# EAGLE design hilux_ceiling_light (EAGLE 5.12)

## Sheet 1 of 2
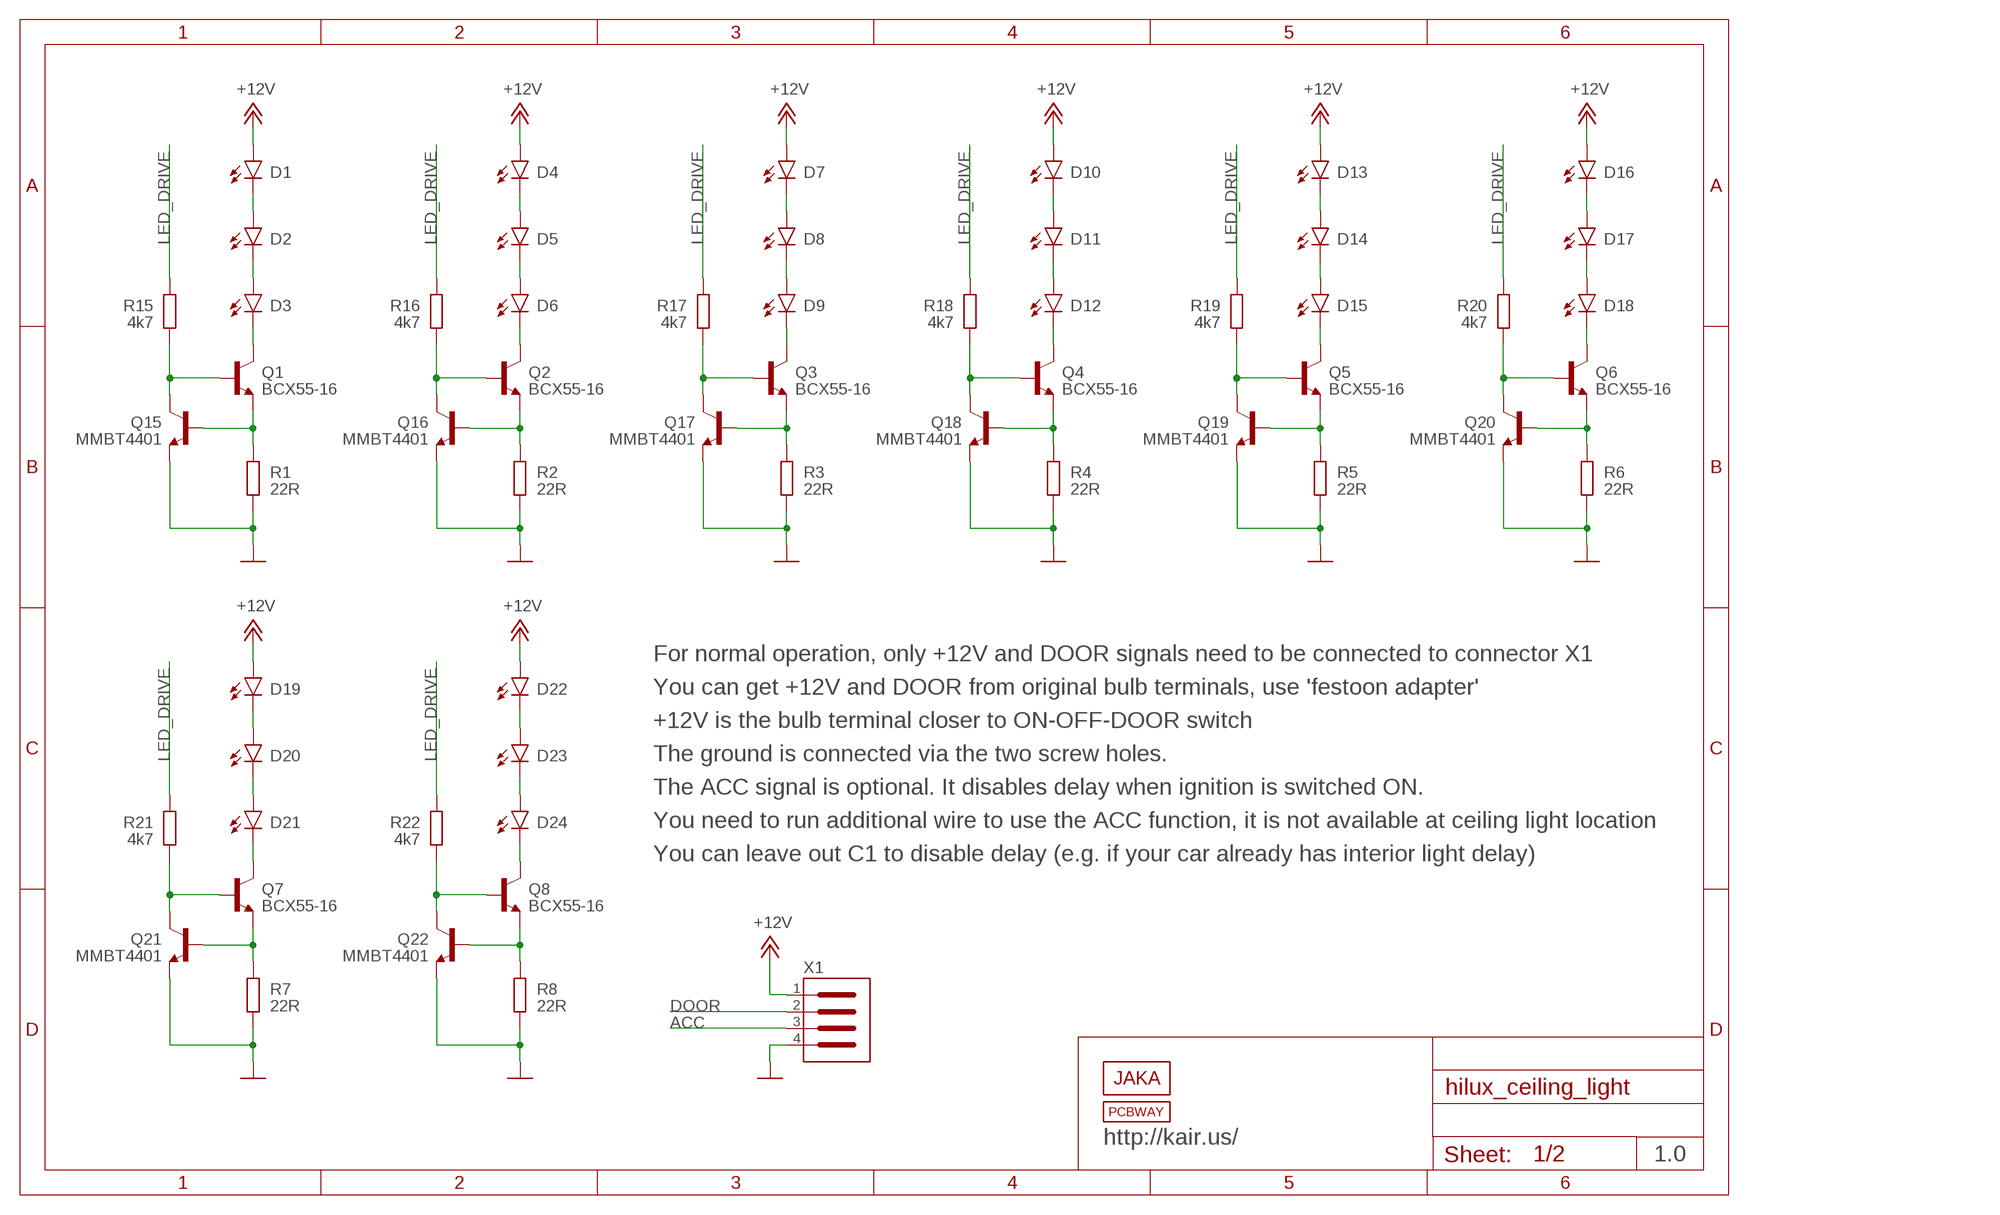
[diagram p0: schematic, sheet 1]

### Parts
D1  CREE_JE2835  [CREE_J2835]
D2  CREE_JE2835  [CREE_J2835]
D3  CREE_JE2835  [CREE_J2835]
D4  CREE_JE2835  [CREE_J2835]
D5  CREE_JE2835  [CREE_J2835]
D6  CREE_JE2835  [CREE_J2835]
D7  CREE_JE2835  [CREE_J2835]
D8  CREE_JE2835  [CREE_J2835]
D9  CREE_JE2835  [CREE_J2835]
D10  CREE_JE2835  [CREE_J2835]
D11  CREE_JE2835  [CREE_J2835]
D12  CREE_JE2835  [CREE_J2835]
D13  CREE_JE2835  [CREE_J2835]
D14  CREE_JE2835  [CREE_J2835]
D15  CREE_JE2835  [CREE_J2835]
D16  CREE_JE2835  [CREE_J2835]
D17  CREE_JE2835  [CREE_J2835]
D18  CREE_JE2835  [CREE_J2835]
D19  CREE_JE2835  [CREE_J2835]
D20  CREE_JE2835  [CREE_J2835]
D21  CREE_JE2835  [CREE_J2835]
D22  CREE_JE2835  [CREE_J2835]
D23  CREE_JE2835  [CREE_J2835]
D24  CREE_JE2835  [CREE_J2835]
LOGO1  PCBWAY_LOGO_SILK_TINY  [PCBWAY_LOGO_SILK_TINY]
Q1  BCX55-16  -NPN-SOT89-BCE  [SOT89-BCE]
Q2  BCX55-16  -NPN-SOT89-BCE  [SOT89-BCE]
Q3  BCX55-16  -NPN-SOT89-BCE  [SOT89-BCE]
Q4  BCX55-16  -NPN-SOT89-BCE  [SOT89-BCE]
Q5  BCX55-16  -NPN-SOT89-BCE  [SOT89-BCE]
Q6  BCX55-16  -NPN-SOT89-BCE  [SOT89-BCE]
Q7  BCX55-16  -NPN-SOT89-BCE  [SOT89-BCE]
Q8  BCX55-16  -NPN-SOT89-BCE  [SOT89-BCE]
Q15  MMBT4401  MMBT4401LT1-NPN-SOT-23-BEC  [SOT-23]
Q16  MMBT4401  MMBT4401LT1-NPN-SOT-23-BEC  [SOT-23]
Q17  MMBT4401  MMBT4401LT1-NPN-SOT-23-BEC  [SOT-23]
Q18  MMBT4401  MMBT4401LT1-NPN-SOT-23-BEC  [SOT-23]
Q19  MMBT4401  MMBT4401LT1-NPN-SOT-23-BEC  [SOT-23]
Q20  MMBT4401  MMBT4401LT1-NPN-SOT-23-BEC  [SOT-23]
Q21  MMBT4401  MMBT4401LT1-NPN-SOT-23-BEC  [SOT-23]
Q22  MMBT4401  MMBT4401LT1-NPN-SOT-23-BEC  [SOT-23]
R1  22R  R-EU_R0805  [R0805]
R2  22R  R-EU_R0805  [R0805]
R3  22R  R-EU_R0805  [R0805]
R4  22R  R-EU_R0805  [R0805]
R5  22R  R-EU_R0805  [R0805]
R6  22R  R-EU_R0805  [R0805]
R7  22R  R-EU_R0805  [R0805]
R8  22R  R-EU_R0805  [R0805]
R15  4k7  R-EU_R0805  [R0805]
R16  4k7  R-EU_R0805  [R0805]
R17  4k7  R-EU_R0805  [R0805]
R18  4k7  R-EU_R0805  [R0805]
R19  4k7  R-EU_R0805  [R0805]
R20  4k7  R-EU_R0805  [R0805]
R21  4k7  R-EU_R0805  [R0805]
R22  4k7  R-EU_R0805  [R0805]
U$1  JAKA_LOGO_MASK_TINY  [JAKA_MASK_TINY]
X1  CON_HEADER_4P  [HEADER_1X04_STAGGERED]

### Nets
+12V: D1.A D4.A D7.A D10.A D13.A D16.A D19.A D22.A X1.1 ; also sheet 2
ACC: X1.3 ; also sheet 2
DOOR: X1.2 ; also sheet 2
GND: Q15.2(E) Q16.2(E) Q17.2(E) Q18.2(E) Q19.2(E) Q20.2(E) Q21.2(E) Q22.2(E) R1.2 R2.2 R3.2 R4.2 R5.2 R6.2 R7.2 R8.2 X1.4 ; also sheet 2
LED_DRIVE: R15.1 R16.1 R17.1 R18.1 R19.1 R20.1 R21.1 R22.1 ; also sheet 2
N$1: Q1.E Q15.1(B) R1.1
N$2: Q1.B Q15.3(C) R15.2
N$4: D2.K D3.A
N$5: D1.K D2.A
N$7: Q2.E Q16.1(B) R2.1
N$8: Q2.B Q16.3(C) R16.2
N$10: D5.K D6.A
N$11: D4.K D5.A
N$13: Q3.E Q17.1(B) R3.1
N$14: Q3.B Q17.3(C) R17.2
N$17: D8.K D9.A
N$18: D7.K D8.A
N$19: Q4.E Q18.1(B) R4.1
N$20: Q4.B Q18.3(C) R18.2
N$22: D11.K D12.A
N$23: D10.K D11.A
N$25: Q5.E Q19.1(B) R5.1
N$26: Q5.B Q19.3(C) R19.2
N$28: D14.K D15.A
N$29: D13.K D14.A
N$31: Q6.E Q20.1(B) R6.1
N$32: Q6.B Q20.3(C) R20.2
N$34: D17.K D18.A
N$35: D16.K D17.A
N$43: Q7.E Q21.1(B) R7.1
N$44: Q7.B Q21.3(C) R21.2
N$46: D20.K D21.A
N$47: D19.K D20.A
N$48: Q8.E Q22.1(B) R8.1
N$49: Q8.B Q22.3(C) R22.2
N$51: D23.K D24.A
N$52: D22.K D23.A
Q1_HEAT: D3.K Q1.C@1(C)
Q2_HEAT: D6.K Q2.C@1(C)
Q3_HEAT: D9.K Q3.C@1(C)
Q4_HEAT: D12.K Q4.C@1(C)
Q5_HEAT: D15.K Q5.C@1(C)
Q6_HEAT: D18.K Q6.C@1(C)
Q7_HEAT: D21.K Q7.C@1(C)
Q8_HEAT: D24.K Q8.C@1(C)

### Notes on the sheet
- For normal operation, only +12V and DOOR signals need to be connected to connector X1
- You can get +12V and DOOR from original bulb terminals, use 'festoon adapter'
- +12V is the bulb terminal closer to ON-OFF-DOOR switch
- The ground is connected via the two screw holes.
- The ACC signal is optional. It disables delay when ignition is switched ON.
- You need to run additional wire to use the ACC function, it is not available at ceiling light location
- You can leave out C1 to disable delay (e.g. if your car already has interior light delay)
- http://kair.us/
- 1.0

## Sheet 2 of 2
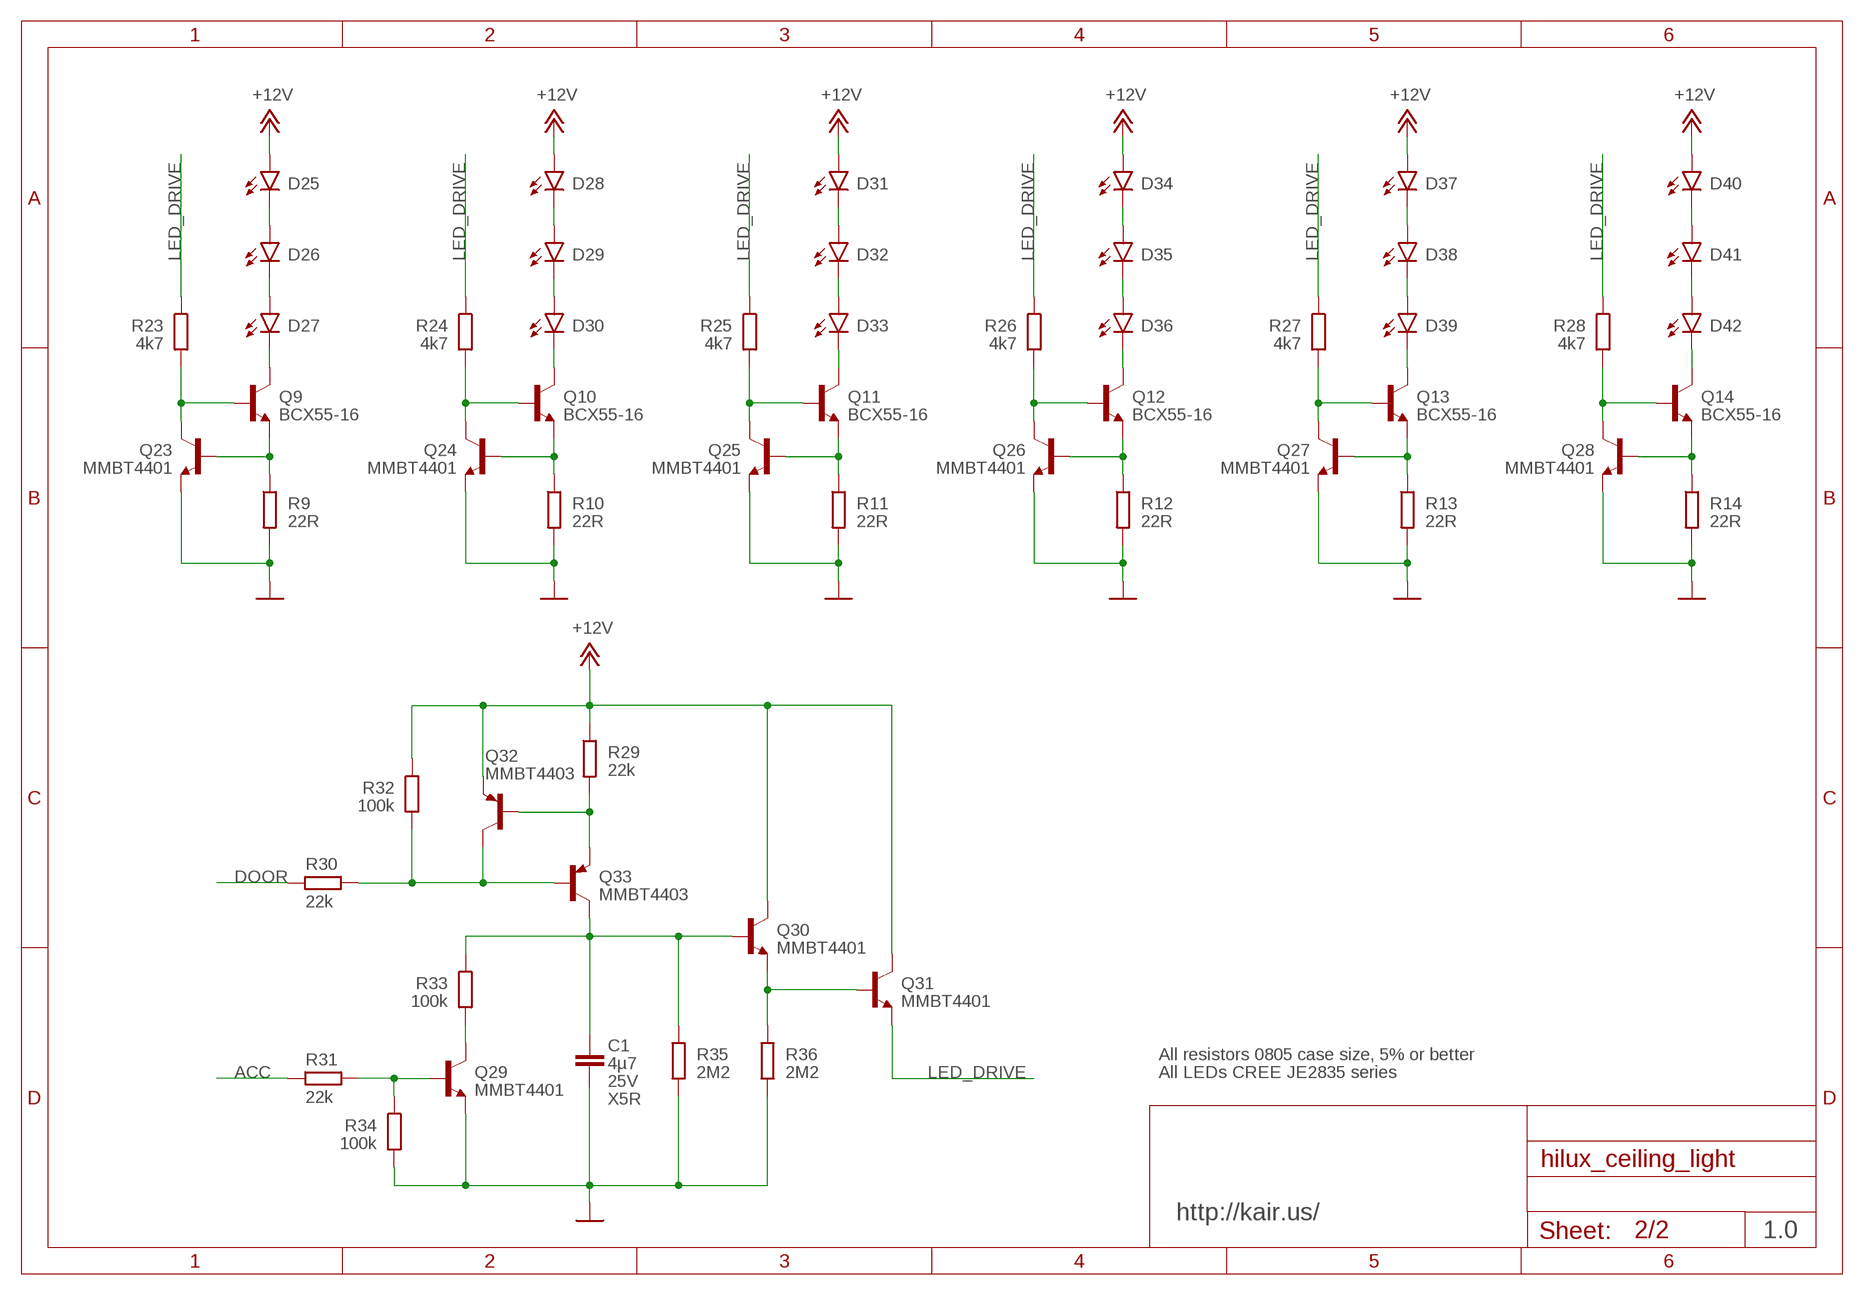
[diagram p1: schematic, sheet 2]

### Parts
C1  4µ7  C-EUC0805  [C0805]
D25  CREE_JE2835  [CREE_J2835]
D26  CREE_JE2835  [CREE_J2835]
D27  CREE_JE2835  [CREE_J2835]
D28  CREE_JE2835  [CREE_J2835]
D29  CREE_JE2835  [CREE_J2835]
D30  CREE_JE2835  [CREE_J2835]
D31  CREE_JE2835  [CREE_J2835]
D32  CREE_JE2835  [CREE_J2835]
D33  CREE_JE2835  [CREE_J2835]
D34  CREE_JE2835  [CREE_J2835]
D35  CREE_JE2835  [CREE_J2835]
D36  CREE_JE2835  [CREE_J2835]
D37  CREE_JE2835  [CREE_J2835]
D38  CREE_JE2835  [CREE_J2835]
D39  CREE_JE2835  [CREE_J2835]
D40  CREE_JE2835  [CREE_J2835]
D41  CREE_JE2835  [CREE_J2835]
D42  CREE_JE2835  [CREE_J2835]
Q9  BCX55-16  -NPN-SOT89-BCE  [SOT89-BCE]
Q10  BCX55-16  -NPN-SOT89-BCE  [SOT89-BCE]
Q11  BCX55-16  -NPN-SOT89-BCE  [SOT89-BCE]
Q12  BCX55-16  -NPN-SOT89-BCE  [SOT89-BCE]
Q13  BCX55-16  -NPN-SOT89-BCE  [SOT89-BCE]
Q14  BCX55-16  -NPN-SOT89-BCE  [SOT89-BCE]
Q23  MMBT4401  MMBT4401LT1-NPN-SOT-23-BEC  [SOT-23]
Q24  MMBT4401  MMBT4401LT1-NPN-SOT-23-BEC  [SOT-23]
Q25  MMBT4401  MMBT4401LT1-NPN-SOT-23-BEC  [SOT-23]
Q26  MMBT4401  MMBT4401LT1-NPN-SOT-23-BEC  [SOT-23]
Q27  MMBT4401  MMBT4401LT1-NPN-SOT-23-BEC  [SOT-23]
Q28  MMBT4401  MMBT4401LT1-NPN-SOT-23-BEC  [SOT-23]
Q29  MMBT4401  MMBT4401LT1-NPN-SOT-23-BEC  [SOT-23]
Q30  MMBT4401  MMBT4401LT1-NPN-SOT-23-BEC  [SOT-23]
Q31  MMBT4401  MMBT4401LT1-NPN-SOT-23-BEC  [SOT-23]
Q32  MMBT4403  MMBT4403LT1-PNP-SOT-23-BEC  [SOT-23]
Q33  MMBT4403  MMBT4403LT1-PNP-SOT-23-BEC  [SOT-23]
R9  22R  R-EU_R0805  [R0805]
R10  22R  R-EU_R0805  [R0805]
R11  22R  R-EU_R0805  [R0805]
R12  22R  R-EU_R0805  [R0805]
R13  22R  R-EU_R0805  [R0805]
R14  22R  R-EU_R0805  [R0805]
R23  4k7  R-EU_R0805  [R0805]
R24  4k7  R-EU_R0805  [R0805]
R25  4k7  R-EU_R0805  [R0805]
R26  4k7  R-EU_R0805  [R0805]
R27  4k7  R-EU_R0805  [R0805]
R28  4k7  R-EU_R0805  [R0805]
R29  22k  R-EU_R0805  [R0805]
R30  22k  R-EU_R0805  [R0805]
R31  22k  R-EU_R0805  [R0805]
R32  100k  R-EU_R0805  [R0805]
R33  100k  R-EU_R0805  [R0805]
R34  100k  R-EU_R0805  [R0805]
R35  2M2  R-EU_R0805  [R0805]
R36  2M2  R-EU_R0805  [R0805]

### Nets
+12V: D25.A D28.A D31.A D34.A D37.A D40.A Q30.3(C) Q31.3(C) Q32.2(E) R29.1 R32.1 ; also sheet 1
ACC: R31.1 ; also sheet 1
DOOR: R30.2 ; also sheet 1
GND: C1.2 Q23.2(E) Q24.2(E) Q25.2(E) Q26.2(E) Q27.2(E) Q28.2(E) Q29.2(E) R9.2 R10.2 R11.2 R12.2 R13.2 R14.2 R34.2 R35.2 R36.2 ; also sheet 1
LED_DRIVE: Q31.2(E) R23.1 R24.1 R25.1 R26.1 R27.1 R28.1 ; also sheet 1
N$37: C1.1 Q30.1(B) Q33.3(C) R33.1 R35.1
N$38: Q32.1(B) Q33.2(E) R29.2
N$39: Q32.3(C) Q33.1(B) R30.1 R32.2
N$40: Q29.3(C) R33.2
N$41: Q30.2(E) Q31.1(B) R36.1
N$42: Q29.1(B) R31.2 R34.1
N$53: Q9.E Q23.1(B) R9.1
N$54: Q9.B Q23.3(C) R23.2
N$56: D26.K D27.A
N$57: D25.K D26.A
N$58: Q10.E Q24.1(B) R10.1
N$59: Q12.E Q26.1(B) R12.1
N$61: D29.K D30.A
N$62: D28.K D29.A
N$63: Q11.E Q25.1(B) R11.1
N$64: Q11.B Q25.3(C) R25.2
N$67: D32.K D33.A
N$68: D31.K D32.A
N$69: Q12.B Q26.3(C) R26.2
N$71: D35.K D36.A
N$72: D34.K D35.A
N$73: Q13.E Q27.1(B) R13.1
N$75: D38.K D39.A
N$76: D37.K D38.A
N$77: Q14.E Q28.1(B) R14.1
N$78: Q14.B Q28.3(C) R28.2
N$81: D41.K D42.A
N$82: D40.K D41.A
Q1: Q13.B Q27.3(C) R27.2
Q9_HEAT: D27.K Q9.C@1(C)
Q10_HEAT: D30.K Q10.C@1(C)
Q11_HEAT: D33.K Q11.C@1(C)
Q12_HEAT: D36.K Q12.C@1(C)
Q13_HEAT: D39.K Q13.C@1(C)
Q14_HEAT: D42.K Q14.C@1(C)
Q24: Q10.B Q24.3(C) R24.2

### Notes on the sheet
- All resistors 0805 case size, 5% or better
- All LEDs CREE JE2835 series
- 25V
- X5R
- http://kair.us/
- 1.0

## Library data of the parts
C1 = omat:C-EU: CAPACITOR, European symbol
D1-D42 = omat:CREE_JE2835
LOGO1 = omat:PCBWAY_LOGO
Q1-Q31 = omat:*-NPN-: NPN Transistror
Q32 Q33 = omat:*-PNP-: PNP Transistror
R1-R36 = omat:R-EU_: RESISTOR, European symbol
U$1 = omat:JAKA_LOGO
X1 = omat:CON_HEADER_4P

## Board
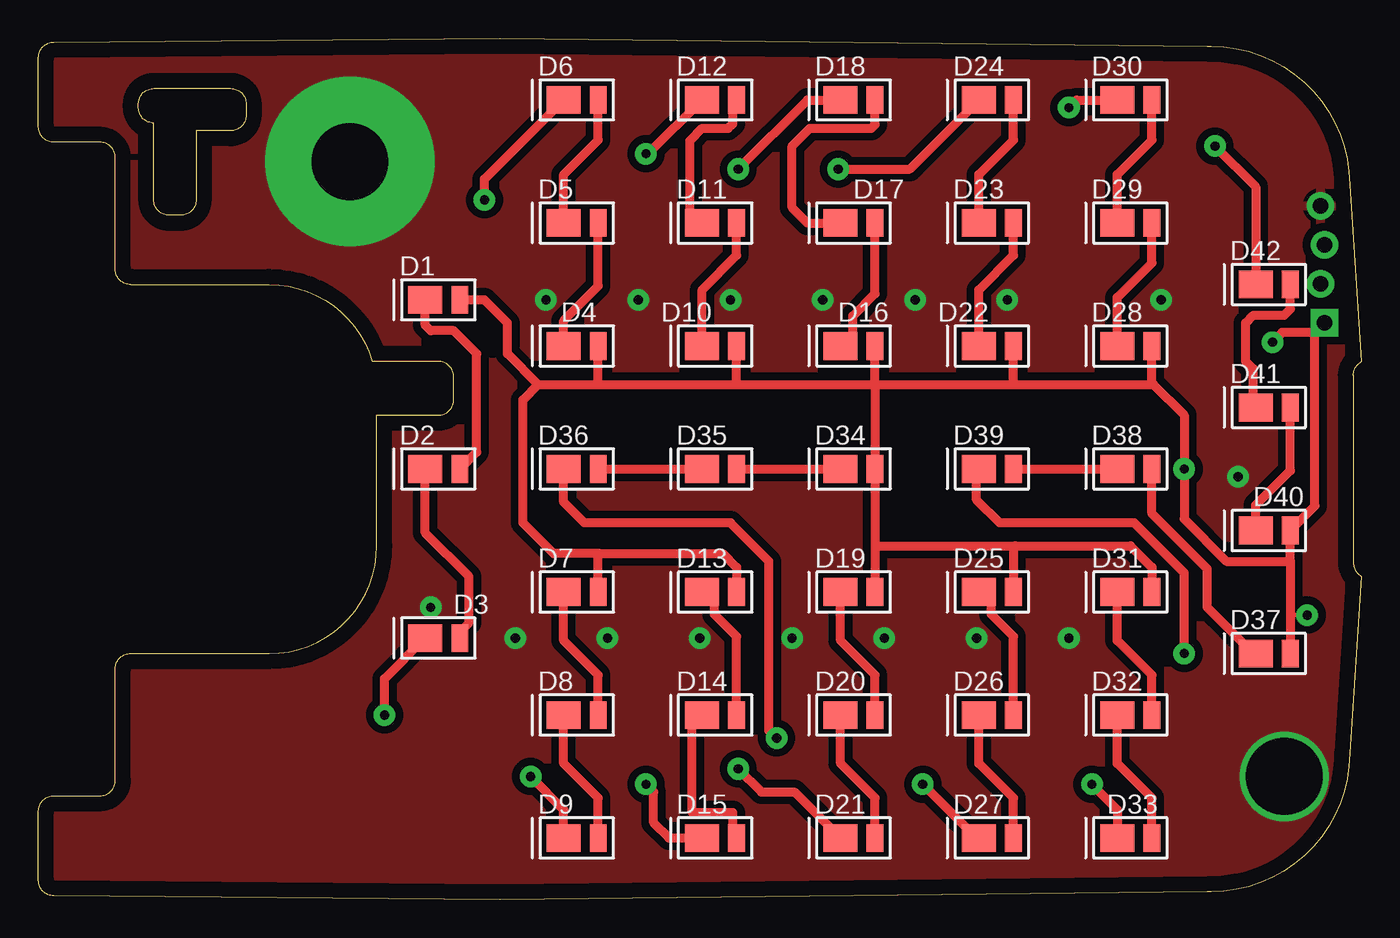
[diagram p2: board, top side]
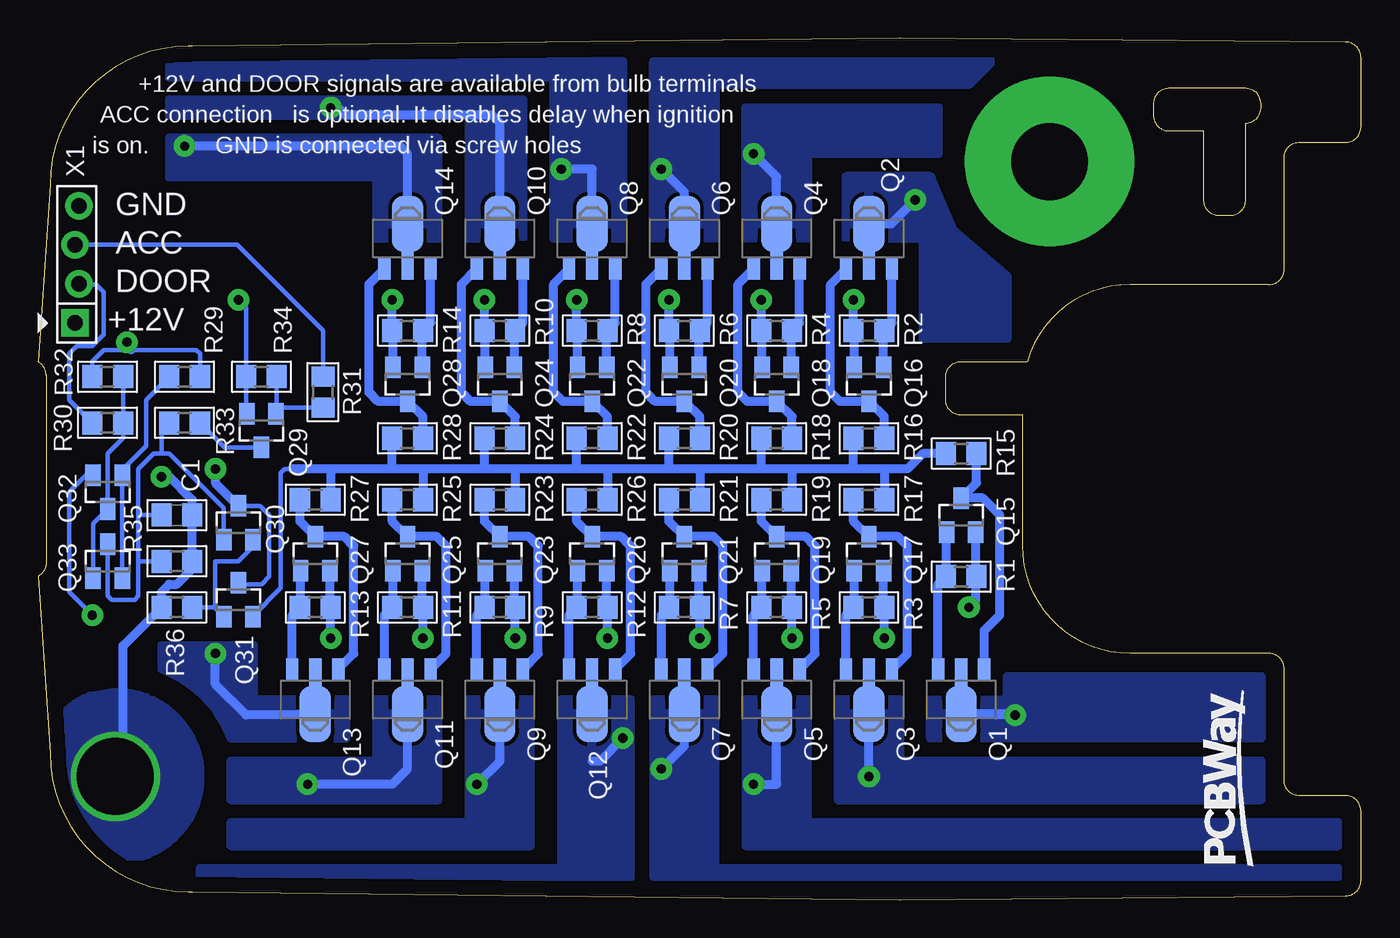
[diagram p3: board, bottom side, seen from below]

Size 86 x 56 mm. Coordinates in mm from the lower left corner, seen from the top.
Outline: 0,5.75 arc-90 1,6.75 4,6.75 arc90 5,7.75 5,15 arc-90 6,16 15,16 arc90 22,23 22,31.5 26,31.5 arc90 27,32.5 27,34 arc90 26,35 21.71,35 arc73 15,40 6,40 arc-90 5,41 5,48.25 arc90 4,49.25 1,49.25 arc-90 0,50.25 0,54.76 arc-90 0.99,55.76 30,56 76,55.5 76.25,55.5 arc-90 85.25,46.5 86,35 85.79,34.79 arc45 85.5,34.09 85.5,21.91 arc45 85.79,21.21 86,21 85.25,9.5 arc-90 76.25,0.5 76,0.5 30,0 0.99,0.24 arc-90 0,1.24 0,5.75
Outline: 10.25,50 10.25,45.5 arc-90 9.25,44.5 8.5,44.5 arc-90 7.5,45.5 7.5,50.5 arc-90 6.5,51.5 6.5,51.75 arc-90 7.5,52.75 12.5,52.75 arc-90 13.5,51.75 13.5,51 arc-90 12.5,50 10.25,50
Copper layers (1*16): Top 0.035mm / dielectric 1.5mm / Bottom 0.035mm
Design rules "default *": minimum track width 0.3mm, minimum drill 0.6mm, track to track 0.3mm, track to pad 0.3mm, pad to pad 0.3mm, via to via 0.3mm, smd to smd 8mil, copper to edge 1mm, drill to drill 0.3mm, minimum pad ring 0.4mm, minimum via ring 0.4mm, stop-mask expansion 4mil, vias tented up to drill 0mil, thermal gap 10mil
tKeepout: area 14.8,42.5 to 25.8,53.5; area 75.5,2.5 to 86.5,13.5
bKeepout: area 0,0 to 86,56; area 80,15 to 83,18; area 24.5,16 to 27.5,19; area 73.5,26.5 to 76.5,29.5; area 11.5,40.5 to 14.5,43.5; area 11,12.5 to 14,15.5

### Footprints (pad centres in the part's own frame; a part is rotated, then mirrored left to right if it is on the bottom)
C0805 = smd 1.3 x 1.5: 1 -1,0; 2 1,0
CREE_J2835 = smd 1.1 x 1.8: A 1.4,0 | smd 2.2 x 1.8: K -0.85,0
SOT89-BCE = smd 0.8 x 1.4: B -1.499,-1.981; E 1.499,-1.981 | smd 2.032 x 3.65: C@1 0,0.94 | smd 0.8 x 1.9: C@2 0,-1.727
SOT-23 = smd 1 x 1.4: 1 -0.95,-1.1; 2 0.95,-1.1; 3 0,1.1
R0805 = smd 1.3 x 1.5: 1 -1,0; 2 1,0
HEADER_1X04_STAGGERED = drill 1 square: 1 0,0.127 | drill 1 round: 2 2.54,-0.127; 3 5.08,0.127; 4 7.62,-0.127

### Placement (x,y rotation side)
C1  77,25 0 bottom
D1  26,39 0 top
D2  26,28 0 top
D3  26,17 0 top
D4  35,36 0 top
D5  35,44 0 top
D6  35,52 0 top
D7  35,20 0 top
D8  35,12 0 top
D9  35,4 0 top
D10  44,36 0 top
D11  44,44 0 top
D12  44,52 0 top
D13  44,20 0 top
D14  44,12 0 top
D15  44,4 0 top
D16  53,36 0 top
D17  53,44 0 top
D18  53,52 0 top
D19  53,20 0 top
D20  53,12 0 top
D21  53,4 0 top
D22  62,36 0 top
D23  62,44 0 top
D24  62,52 0 top
D25  62,20 0 top
D26  62,12 0 top
D27  62,4 0 top
D28  71,36 0 top
D29  71,44 0 top
D30  71,52 0 top
D31  71,20 0 top
D32  71,12 0 top
D33  71,4 0 top
D34  53,28 0 top
D35  44,28 0 top
D36  35,28 0 top
D37  80,16 0 top
D38  71,28 0 top
D39  62,28 0 top
D40  80,24 0 top
D41  80,32 0 top
D42  80,40 0 top
LOGO1  8.5,8 90 bottom
Q1  26,13 180 bottom
Q2  32,43 0 bottom
Q3  32,13 180 bottom
Q4  38,43 0 bottom
Q5  38,13 180 bottom
Q6  44,43 0 bottom
Q7  44,13 180 bottom
Q8  50,43 0 bottom
Q9  56,13 180 bottom
Q10  56,43 0 bottom
Q11  62,13 180 bottom
Q12  50,13 180 bottom
Q13  68,13 180 bottom
Q14  62,43 0 bottom
Q15  26,25 0 bottom
Q16  32,33.5 180 bottom
Q17  32,22.5 0 bottom
Q18  38,33.5 180 bottom
Q19  38,22.5 0 bottom
Q20  44,33.5 180 bottom
Q21  44,22.5 0 bottom
Q22  50,33.5 180 bottom
Q23  56,22.5 0 bottom
Q24  56,33.5 180 bottom
Q25  62,22.5 0 bottom
Q26  50,22.5 0 bottom
Q27  68,22.5 0 bottom
Q28  62,33.5 180 bottom
Q29  71.5,30.5 180 bottom
Q30  73,24.5 0 bottom
Q31  73,19.5 0 bottom
Q32  81.5,26.5 180 bottom
Q33  81.5,22 0 bottom
R1  26,21 0 bottom
R2  32,37 180 bottom
R3  32,19 0 bottom
R4  38,37 180 bottom
R5  38,19 0 bottom
R6  44,37 180 bottom
R7  44,19 0 bottom
R8  50,37 180 bottom
R9  56,19 0 bottom
R10  56,37 180 bottom
R11  62,19 0 bottom
R12  50,19 0 bottom
R13  68,19 0 bottom
R14  62,37 180 bottom
R15  26,29 0 bottom
R16  32,30 0 bottom
R17  32,26 180 bottom
R18  38,30 0 bottom
R19  38,26 180 bottom
R20  44,30 0 bottom
R21  44,26 180 bottom
R22  50,30 0 bottom
R23  56,26 180 bottom
R24  56,30 0 bottom
R25  62,26 180 bottom
R26  50,26 180 bottom
R27  68,26 180 bottom
R28  62,30 0 bottom
R29  76.5,34 180 bottom
R30  81.5,31 180 bottom
R31  67.5,33 270 bottom
R32  81.5,34 0 bottom
R33  76.5,31 0 bottom
R34  71.5,34 180 bottom
R35  77,22 0 bottom
R36  77,19 180 bottom
U$1  12.3,10.6 0 top
U$2  [A4L-LOC]  not placed on the board
X1  83.5,37.5 90 bottom

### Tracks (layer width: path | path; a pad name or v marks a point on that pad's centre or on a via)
+12V  (via drill 0.6)
  Top 0.3: 81.4,18.5 v82.5,18.5
  Top 0.6: D1.A 29,39 30.5,37.5 30.5,35.5 32.5,33.5 | 32.5,33.5 36.5,33.5 | 36.5,33.5 45.5,33.5 | 45.5,33.5 54.5,33.5 | 54.5,33.5 63.5,33.5 | 63.5,33.5 72.5,33.5 | 72.5,33.5 74.5,31.5 v74.5,28 74.5,24.75 77.25,22 81.4,22 | D28.A 72.4,33.6 72.5,33.5 | D22.A 63.4,33.6 63.5,33.5 | D16.A 54.4,33.6 54.5,33.5 | D10.A 45.4,33.6 45.5,33.5 | D4.A 36.4,33.6 36.5,33.5 | 32.5,33.5 31.5,32.5 31.5,24.5 33.5,22.5 36.5,22.5 | D13.A 45.4,21.6 44.5,22.5 36.5,22.5 | D7.A 36.4,22.4 36.5,22.5 | 54.4,23 D34.A 54.4,33.4 54.5,33.5 | 54.4,23 D19.A | D31.A 72.4,21.6 71,23 63.5,23 | 54.4,23 63.5,23 | D25.A 63.4,22.9 63.5,23 | 83,36.87 X1.1 | 83,36.87 83,25.6 D40.A 81.4,22 | 81.4,22 81.4,18.5 D37.A | 83,36.87 80.87,36.87 v80.25,36.25
  Bottom 0.3: Q31.3 72.9,20.5 72,20.5 71.5,20.5 71,21 71,25 71.6,25.6 Q30.3 | Q32.2 82.9,27.6 84,26.5 84,20 v82.5,18.5 | R32.1 82.5,35 81.75,35.75 80,35.75 75.75,35.75 75.5,35.5 R29.1
  Bottom 0.6: Q30.3 74.5,27.1 v74.5,28 | v80.25,36.25 80.25,36 80,35.75
ACC
  Bottom 0.3: X1.3 73.08,42.58 67.5,37 R31.1
DOOR
  Bottom 0.3: X1.2 83.33,40 82.25,40 81.75,39.5 81.75,36.75 82.5,36 83.5,36 84,35.5 84,32.5 R30.2
GND  (via drill 0.6, 5 pad 11, 5 pad 5.5)
  Bottom 0.3: Q29.2 72.5,31.65 R34.2 72.5,38.5 v73,39
  Bottom 0.6: 25.05,21.05 Q15.2 | 25.05,21.05 R1.2 | Q19.2 37.05,19.05 R5.2 v37,17 | Q21.2 43.05,19.05 R7.2 v43,17 | Q26.2 49.05,19.05 R12.2 v49,17 | Q23.2 55.05,19.05 R9.2 v55,17 | Q25.2 61.05,19.05 R11.2 v61,17 | Q27.2 67.05,19.05 R13.2 v67,17 | v31,17 R3.2 31.05,19.05 Q17.2 | Q16.2 32.95,36.95 R2.2 v33,39 | Q18.2 38.95,36.95 R4.2 v39,39 | Q20.2 44.95,36.95 R6.2 v45,39 | Q22.2 50.95,36.95 R8.2 v51,39 | Q24.2 56.95,36.95 R10.2 v57,39 | Q28.2 62.95,36.95 R14.2 v63,39 | 25.05,21.05 25.05,19.45 v25.5,19 | v81,8 80.5,8.5 80.5,16.5 R36.2 78,20 77.5,20.5 77,20.5 76,21.5 R35.2 C1.2 76,26 77.5,27.5 v78,27.5
  other vias: 20.25,48
  pour Top (isolate 0.5): 0,0 86,0 86,53 86,56 0,56
  pour Bottom: 81,13.5 arc90 75.5,8 arc72 79.3,2.8 81.65,2.7 83.75,5.95 84.3,7.9 85.05,11.6 84.15,12.27 arc23 82.66,13.22
LED_DRIVE
  Bottom 0.3: 69.5,28 70,28 70.25,27.75 70.25,20.25 72.05,18.45 Q31.2
  Bottom 0.6: 31,28 29.5,28 28.5,29 R15.1 | 31,28 33,28 | 33,28 37,28 | 37,28 39,28 | 39,28 43,28 | 43,28 45,28 | 45,28 49,28 | 49,28 51,28 | 51,28 55,28 | 55,28 57,28 | 57,28 61,28 | 61,28 63,28 | 63,28 67,28 | 67,28 69.5,28 | 31,28 R17.1 | 33,28 R16.1 | 37,28 R19.1 | 39,28 R18.1 | 43,28 R21.1 | 45,28 R20.1 | 49,28 R26.1 | 51,28 R22.1 | 55,28 R23.1 | 57,28 R24.1 | 61,28 R25.1 | 63,28 R28.1 | 67,28 R27.1
N$1
  Bottom 0.6: Q1.E 27.5,20.5 R1.1 26.95,21.05 Q15.1
N$2
  Bottom 0.6: Q1.B 24.5,17.5 23.5,18.5 23.5,25 24.6,26.1 Q15.3 | Q15.3 25.9,26 | R15.2 25,27.1 Q15.3
N$4
  Top 0.6: D2.K 25.15,23.85 28,21 28,18 27.4,17.4 D3.A
N$5
  Top 0.6: D1.K 25.15,37.35 25.5,37 27,37 28.5,35.5 28.5,29.1 D2.A
N$7
  Bottom 0.6: Q2.E 30.5,37.5 R2.1 31.05,36.95 Q16.1
N$8
  Bottom 0.6: R16.2 31,31.4 Q16.3 33.9,32.4 34.5,33 34.5,40 33.5,41 Q2.B
N$10
  Top 0.6: D6.A 36.4,49.4 34.15,47.15 D5.K
N$11
  Top 0.6: D5.A 36.4,39.9 34.15,37.65 D4.K
N$13
  Bottom 0.6: Q17.1 32.95,19.05 R3.1 33.5,18.5 Q3.E
N$14
  Bottom 0.6: Q3.B 29.5,15.98 29.5,23 30.1,23.6 Q17.3 33,24.6 R17.2
N$17
  Top 0.6: D8.K 34.15,8.85 36.4,6.6 D9.A
N$18
  Top 0.6: D7.K 34.15,16.85 36.4,14.6 D8.A
N$19
  Bottom 0.6: Q18.1 37.05,36.95 R4.1 36.5,37.5 Q4.E
N$20
  Bottom 0.6: R18.2 37,31.4 Q18.3 39.9,32.4 40.5,33 40.5,40.02 Q4.B
N$22
  Top 0.6: D12.A 45.15,51.75 45.15,50.45 44.85,50.15 43.15,50.15 42.35,49.35 42.35,44.25 42.6,44 D11.K
N$23
  Top 0.6: D11.A 45.4,41.9 43.15,39.65 D10.K
N$25
  Bottom 0.6: Q5.E 39.5,18.5 R5.1 38.95,19.05 Q19.1
N$26
  Bottom 0.6: R19.2 39,24.6 Q19.3 36.1,23.6 35.5,23 35.5,15.98 Q5.B
N$28
  Top 0.6: D15.A 45.15,4 45.15,5.65 42.5,5.65 42.5,11.35 D14.K
N$29
  Top 0.6: D14.A 45.4,17.1 43.95,18.55 43.95,19.5 43.45,20 D13.K
N$31
  Bottom 0.6: Q20.1 43.05,36.95 R6.1 42.5,37.5 Q6.E
N$32
  Bottom 0.6: R20.2 43,31.4 Q20.3 45.9,32.4 46.5,33 46.5,40.02 Q6.B
N$34
  Top 0.6: D18.A 54.4,50.4 54.15,50.15 50.15,50.15 49,49 49,45 50,44 D17.K
N$35
  Top 0.6: D17.A 54.4,39.4 52.95,37.95 52.95,36.4 52.55,36 D16.K
N$37
  Bottom 0.3: 78,29 78,30.5 R33.1 | 79.5,22 79.5,25 | 79.5,25 79.5,28 78.5,29 78,29 | Q30.1 73.95,25.45 77.5,29 78,29 | R35.1 79.5,22 | 79.5,25 C1.1 | 79.5,22 79.5,19.75 79.75,19.5 81.25,19.5 81.5,19.75 Q33.3
N$38
  Bottom 0.3: Q33.2 Q32.1 80.55,27.95 79,29.5 79,32.5 R29.2
N$39
  Bottom 0.3: Q33.1 82.45,24.45 Q32.3 81.5,29 80.5,30 R32.2 R30.1
N$40
  Bottom 0.3: Q29.3 73.9,29.4 R33.2
N$41
  Bottom 0.3: 74.55,19 R36.1 | Q31.1 74.55,19 | Q30.2 72.05,22.95 73,22 74.5,22 74.5,19.05 74.55,19
N$42
  Bottom 0.3: R31.2 70.15,32 Q29.1 70.5,31.65 R34.1
N$43
  Bottom 0.6: Q21.1 44.95,19.05 R7.1 45.5,18.5 Q7.E
N$44
  Bottom 0.6: Q7.B 42.5,15 41.5,16 41.5,23 42.1,23.6 Q21.3 45,24.6 R21.2
N$46
  Top 0.6: D20.K 52.15,8.85 54.4,6.6 D21.A
N$47
  Top 0.6: D19.K 52.15,16.85 54.4,14.6 D20.A
N$48
  Bottom 0.6: Q22.1 49.05,36.95 R8.1 48.5,37.5 Q8.E
N$49
  Bottom 0.6: R22.2 49,31.4 Q22.3 51.9,32.4 52.5,33 52.5,40.02 Q8.B
N$51
  Top 0.6: D24.A 63.4,49.4 61.15,47.15 D23.K
N$52
  Top 0.6: D23.A 63.4,41.9 61.15,39.65 D22.K
N$53
  Bottom 0.6: Q23.1 56.95,19.05 R9.1 57.5,18.5 Q9.E
N$54
  Bottom 0.6: R23.2 57,24.6 Q23.3 54.1,23.6 53.5,23 53.5,15.98 Q9.B
N$56
  Top 0.6: D27.A 63.4,6.6 61.15,8.85 D26.K
N$57
  Top 0.6: D26.A 63.4,17.1 61.95,18.55 61.95,19.2 D25.K
N$58
  Bottom 0.6: Q24.1 55.05,36.95 R10.1 54.5,37.5 Q10.E
N$59
  Bottom 0.6: Q26.1 50.95,19.05 R12.1 51.5,18.5 Q12.E
N$61
  Top 0.6: D30.A 72.4,49.4 70.15,47.15 D29.K
N$62
  Top 0.6: D29.A 72.4,41.4 70.15,39.15 D28.K
N$63
  Bottom 0.6: Q25.1 62.95,19.05 R11.1 63.5,18.5 Q11.E
N$64
  Bottom 0.6: R25.2 63,24.6 Q25.3 60.1,23.6 59.5,23 59.5,15.98 Q11.B
N$67
  Top 0.6: D32.K 70.15,8.85 72.4,6.6 D33.A
N$68
  Top 0.6: D31.K 70.15,16.85 72.4,14.6 D32.A
N$69
  Bottom 0.6: R26.2 51,24.6 Q26.3 48.1,23.6 47.5,23 47.5,15.98 Q12.B
N$71
  Top 0.6: D36.A D35.K
N$72
  Top 0.6: D35.A D34.K
N$73
  Bottom 0.6: Q27.1 68.95,19.05 R13.1 69.5,18.5 Q13.E
N$75
  Top 0.6: D39.A D38.K
N$76
  Top 0.6: D37.K 79,16 76,19 76,21.5 72.4,25.1 D38.A
N$77
  Bottom 0.6: Q28.1 61.05,36.95 R14.1 60.5,37.5 Q14.E
N$78
  Bottom 0.6: R28.2 61,31.4 Q28.3 63.9,32.4 64.5,33 64.5,40.02 Q14.B
N$81
  Top 0.6: D42.A 81.4,38.4 81,38 79,38 78.5,37.5 78.5,35 79,34.5 79,32.15 D41.K
N$82
  Top 0.6: D41.A 81.4,27.9 79.15,25.65 D40.K
Q1
  Bottom 0.6: R27.2 69,24.6 Q27.3 66.1,23.6 65.5,23 65.5,16 66.5,15 Q13.B
Q1_HEAT  (via drill 0.6)
  Top 0.6: D3.K 22.5,14.35 v22.5,12
  Bottom 0.6: Q1.C@1 26,13 25,12 v22.5,12 22.56,12.06 Q1.C@1
  pour Bottom: 28,13 23,13 23,14.5 6.5,14.5 6.5,10.5 28,10.5
Q2_HEAT  (via drill 0.6)
  Top 0.6: D6.K 29,46.85 v29,45.5
  Bottom 0.6: v29,45.5 30.56,43.94 Q2.C@1
  pour Bottom: 33.5,43 28.5,43 28.5,36.5 23,36.5 23,40.5 26.5,43.5 28,47 33.5,47
Q3_HEAT  (via drill 0.6)
  Top 0.6: D9.K 34.15,5.85 v32,8
  Bottom 0.6: v32,8 Q3.C@1
  pour Bottom: 30,13 34,13 34,6.5 6.5,6.5 6.5,9 30,9
Q4_HEAT  (via drill 0.6)
  Top 0.6: D12.K 39.65,48.5 v39.5,48.5
  Bottom 0.6: v39.5,48.5 38,47 38,44
  pour Bottom: 40,43 40,51.5 27.5,51.5 27.5,48.5 36,48.5 36,43
Q5_HEAT  (via drill 0.6)
  Top 0.6: D15.K 41,4 40,5 40,7 v39.5,7.5
  Bottom 0.6: Q5.C@1 38,7.5 v39.5,7.5
  pour Bottom: 36,13 40,13 40,3.5 1.5,3.5 1.5,5 36,5
Q6_HEAT  (via drill 0.6)
  Top 0.6: v45.5,47.5 50,52 D18.K
  Bottom 0.6: v45.5,47.5 44,46 44,44
  pour Bottom: 46,43 46,54.5 24,54.5 25.5,53 30,53 42,53 42,43
Q7_HEAT  (via drill 0.6)
  Top 0.6: v45.5,8.5 47,7 49.15,7 D21.K
  Bottom 0.6: v45.5,8.5 44,10 44,12
  pour Bottom: 42,13 46,13 46,1.5 1.5,1.5 1.5,2 42,2
Q8_HEAT  (via drill 0.6)
  Top 0.6: D24.K 56.65,47.5 v52,47.5
  Bottom 0.6: v52,47.5 50,47.5 50,44
  pour Bottom: 48,43 48,54.5 77.5,54.5 77.5,53.5 52.5,53.5 52.5,43
Q9_HEAT  (via drill 0.6)
  Top 0.6: D27.K 61,4 v57.5,7.5
  Bottom 0.6: v57.5,7.5 56,9 Q9.C@1
  pour Bottom: 58,13 58,5 73.5,5 73.5,3.5 54,3.5 54,13
Q10_HEAT  (via drill 0.6)
  Top 0.6: v67,51.5 67.5,52 D30.K
  Bottom 0.6: v67,51.5 67,51 66.5,51.5 66,51 56.5,51 56,50.5 Q10.C@1
  pour Bottom: 54.5,43 54.5,52 77.5,52 77.5,51 58,51 58,43
Q11_HEAT  (via drill 0.6)
  Top 0.6: D33.K 70.15,5.85 v68.5,7.5
  Bottom 0.6: v68.5,7.5 63,7.5 62,8.5 Q11.C@1
  pour Bottom: 60.5,13 64,13 64,10 64,9 73.5,9 73.5,6.5 60.5,6.5 60,6.5 60,13
Q12_HEAT  (via drill 0.6)
  Top 0.6: D36.K 34.15,25.85 35.5,24.5 45,24.5 47.5,22 47.5,11 v48,10.5
  Bottom 0.6: v48,10.5 49.5,9 50,9
  pour Bottom: 47.5,13 52,13 52,2 75.5,2 75.5,1.5 47.5,1.5
Q13_HEAT  (via drill 0.6)
  Top 0.6: D39.K 61,27.85 61,26 62.5,24.5 71.25,24.5 74.5,21.25 v74.5,16
  Bottom 0.6: v74.5,16 74.5,14 72.5,12 68.06,12 Q13.C@1
  pour Bottom: 66,13 72,13 72,16.5 78,16.5 78,15 arc50 73.5,10.5 66,10.5
Q14_HEAT  (via drill 0.6)
  Top 0.6: D42.K 79.15,46.35 v76.5,49
  Bottom 0.6: v76.5,49 62.5,49 62,48.5 Q14.C@1
  pour Bottom: 60,43 60,49.5 77.5,49.5 77.5,47 64,47 64,43
Q24
  Bottom 0.6: R24.2 55,31.4 Q24.3 57.9,32.4 58.5,33 58.5,40.02 Q10.B

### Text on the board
bPlace: +12V and DOOR signals are available from bulb terminals | ACC connection is optional. It disables delay when ignition | GND is connected via screw holes | is on. | GND | ACC | DOOR | +12V
tStop: 2020 | Hilux ceiling light | WWW.KAIR.US
Document: http://kair.us/
_tsilk: D6 | D12 | D18 | D24 | D30 | D5 | D11 | D17 | D23 | D29 | D42 | D1 | D4 | D10 | D16 | D22 | D28 | D41 | D2 | D36 | D35 | D34 | D39 | D38 | D40 | D7 | D13 | D19 | D25 | D31 | D3 | D37 | D8 | D14 | D20 | D26 | D32 | D9 | D15 | D21 | D27 | D33
_bsilk: +12V and DOOR signals are available from bulb terminals | ACC connection is optional. It disables delay when ignition | GND is connected via screw holes | is on. | X1 | Q2 | Q4 | Q6 | Q8 | Q10 | Q14 | GND | ACC | DOOR | +12V | R2 | R4 | R6 | R8 | R10 | R14 | R34 | R29 | R32 | Q16 | Q18 | Q20 | Q22 | Q24 | Q28 | R31 | R33 | R30 | R15 | R16 | R18 | R20 | R22 | R24 | R28 | Q29 | C1 | R17 | R19 | R21 | R26 | R23 | R25 | R27 | Q32 | Q15 | R35 | Q30 | R1 | Q17 | Q19 | Q21 | Q26 | Q23 | Q25 | Q27 | Q33 | R3 | R5 | R7 | R12 | R9 | R11 | R13 | Q31 | R36 | Q1 | Q3 | Q5 | Q7 | Q9 | Q11 | Q13 | Q12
